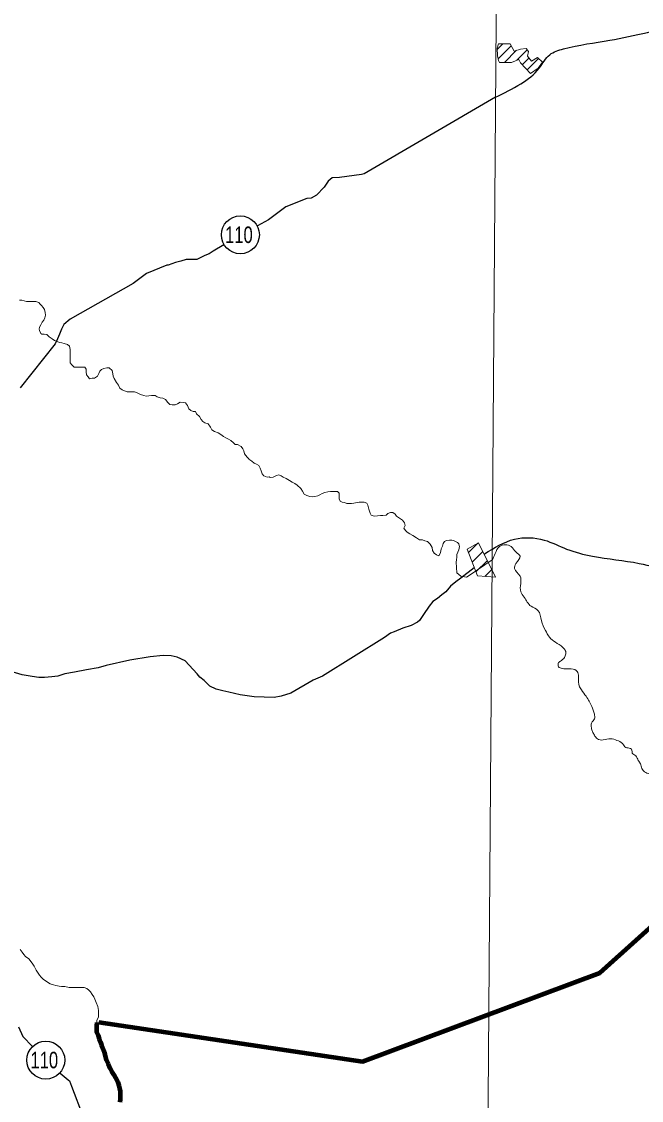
# Model space of a CAD drawing. Extents: x 553962 to 842807, y 8883888 to 9032388.
# Drawn here: x 616530 to 619151, y 8902192 to 8906757 of the extents above; entities that cross this region are included whole.
import ezdxf
from ezdxf.enums import TextEntityAlignment as Align

# ---------------------------------------------------------------- set-up
doc = ezdxf.new("R2010")
doc.units = 0
doc.header["$LTSCALE"] = 160
doc.layers.add('6', color=7, linetype='Continuous', lineweight=13)

msp = doc.modelspace()

# ---------------------------------------------------------------- linework, layer by layer
at = {"layer": '6'}
for p, q in [((618541.3, 8906638.8), (618565.2, 8906662.7)), ((618544.4, 8906599.4), (618599.8, 8906654.9)), ((618571.2, 8906583.9), (618623, 8906635.6)), ((618623.2, 8906593.4), (618667.4, 8906637.6)), ((618647.2, 8906575), (618675.6, 8906603.4)), ((618667.4, 8906552.7), (618715.2, 8906600.5)), ((618419.3, 8904510), (618459.5, 8904550.2)), ((618435.1, 8904469.2), (618480.5, 8904514.6)), ((618451, 8904428.5), (618499.1, 8904476.6)), ((618488.1, 8904409.1), (618517.7, 8904438.6))]:
    msp.add_line(p, q, dxfattribs=at)
for points in [[(618663, 8924716.1), (618558.3, 8909803.7), (618472.6, 8898203.5)], [(616520.7, 8905578.7), (616530.4, 8905578.1), (616540.1, 8905575.7), (616551, 8905573.2), (616566.8, 8905573.2), (616579.5, 8905573.2), (616589.8, 8905572), (616602.6, 8905568.4), (616607.5, 8905563.1), (616614.5, 8905555.9), (616620.6, 8905547.7), (616626.6, 8905538.5), (616629.6, 8905526.2), (616630.5, 8905514), (616627.4, 8905503.8), (616623.2, 8905493.7), (616616.5, 8905485.2), (616611.7, 8905474.3), (616606.2, 8905463.3), (616604.4, 8905455.4), (616605, 8905450), (616611.1, 8905437.2), (616614.7, 8905433.6), (616624.9, 8905433.6), (616637.1, 8905432.5), (616646.2, 8905423.2), (616659.3, 8905414), (616668.4, 8905406.8), (616679.6, 8905402.6), (616689.8, 8905398.5), (616699.9, 8905397.4), (616710.1, 8905395.3), (616724.3, 8905390.1), (616732.4, 8905382.9)], [(616732.4, 8905382.9), (616735.3, 8905369.7), (616735.3, 8905359.5), (616735.2, 8905344.2), (616735, 8905325.9), (616734.9, 8905312.6), (616742, 8905304.4), (616752.1, 8905295.2), (616762.3, 8905294.1), (616773.5, 8905294.1), (616784.7, 8905294), (616796.9, 8905294.9), (616802.9, 8905285.7), (616802.8, 8905275.5), (616804.8, 8905262.3), (616810.8, 8905254.1), (616816.9, 8905244.9), (616828.1, 8905247.9), (616838.2, 8905247.8), (616850.5, 8905255.9), (616856.7, 8905268.1), (616860.8, 8905277.2), (616867, 8905285.3), (616877.2, 8905288.3), (616890.4, 8905291.3), (616900.6, 8905291.2), (616912.7, 8905279.9), (616915.7, 8905266.7), (616916.6, 8905256.5), (616921.7, 8905246.2), (616931.7, 8905229.9), (616939.8, 8905218.6), (616945.8, 8905205.3), (616954.9, 8905199.2), (616965, 8905194), (616976.2, 8905190.9), (616986.4, 8905190.8)], [(616986.4, 8905190.8), (616996.5, 8905190.7), (617006.7, 8905189.7), (617018.9, 8905185.5), (617032.1, 8905179.3), (617046.3, 8905175.1), (617056.4, 8905172), (617067.6, 8905173), (617078.8, 8905174.9), (617094.1, 8905174.8), (617103.2, 8905169.7), (617116.4, 8905165.5), (617127.6, 8905163.4), (617137.7, 8905158.2), (617148.8, 8905144.9), (617156.9, 8905136.7), (617167.1, 8905135.7), (617179.3, 8905135.6), (617188.5, 8905139.6), (617200.7, 8905146.6), (617212.9, 8905144.5), (617223.1, 8905143.4), (617231.1, 8905132.2), (617237.1, 8905118.9), (617245.2, 8905110.7), (617255.4, 8905107.6), (617265.5, 8905106.5), (617269.5, 8905097.3), (617281.7, 8905086), (617289.7, 8905073.7), (617295.8, 8905064.5), (617304.9, 8905058.4), (617319.1, 8905054.2), (617329.2, 8905040.9), (617334.2, 8905029.7), (617345.3, 8905022.4), (617361.6, 8905016.2), (617371.7, 8905010.1), (617383.8, 8905001.8), (617392.9, 8904995.7), (617404.1, 8904990.5), (617415.2, 8904984.3), (617425.3, 8904975.1), (617432.4, 8904966.9), (617442.6, 8904966.8), (617458.8, 8904958.6), (617464.8, 8904949.3), (617469.9, 8904940.1), (617472.8, 8904927.9), (617483.6, 8904913.2), (617490, 8904906.8), (617490, 8904904.7), (617503.1, 8904897.1), (617513.3, 8904888.9), (617523.5, 8904884.2), (617532.9, 8904877.9), (617539.1, 8904867), (617542.2, 8904856.1), (617546.9, 8904843.6), (617554.7, 8904834.2), (617568.8, 8904829.5), (617576.6, 8904831.1), (617581.2, 8904827.9), (617594.2, 8904829.3), (617607.5, 8904836.4)], [(617607.5, 8904836.4), (617617.7, 8904839.4), (617627.8, 8904835.2), (617635.9, 8904829.1), (617649.1, 8904822.9), (617662.3, 8904815.6), (617674.4, 8904808.4), (617684.6, 8904802.2), (617695.7, 8904795.1), (617709.9, 8904780.7), (617716.9, 8904769.4), (617725, 8904757.2), (617736.1, 8904751), (617748.3, 8904746.8), (617758.4, 8904745.8), (617769.6, 8904746.7), (617781.9, 8904749.7), (617791.1, 8904753.7), (617800.2, 8904759.7), (617812.5, 8904763.7), (617824.7, 8904767.7), (617835.9, 8904768.7), (617855.2, 8904768.6), (617865.4, 8904768.5), (617872.5, 8904761.3), (617872.4, 8904748.1), (617872.3, 8904737.9), (617876.3, 8904727.7), (617885.5, 8904723.5), (617895.6, 8904722.4), (617904.7, 8904718.3), (617914.9, 8904718.2), (617925.1, 8904718.2), (617935.3, 8904719.1), (617957.7, 8904723.1), (617967.8, 8904723), (617979, 8904724)], [(617979, 8904724), (617989.2, 8904719.8), (617993.2, 8904710.6), (617998.2, 8904693.3), (618004.1, 8904676.9), (618008.2, 8904667.7), (618020.3, 8904663.6), (618034.6, 8904665.5), (618046.8, 8904667.5), (618057, 8904667.4), (618071.2, 8904668.3), (618078.4, 8904675.4), (618089.6, 8904679.4), (618099.8, 8904679.4), (618108.9, 8904672.2), (618114.9, 8904664), (618124.1, 8904658.8), (618132.2, 8904652.7), (618140.2, 8904646.5), (618148.3, 8904635.3), (618151.3, 8904625.1), (618146.1, 8904612.9), (618153.2, 8904603.6), (618160.2, 8904596.5), (618171.4, 8904589.3), (618184.6, 8904582.1), (618199.8, 8904572.8), (618212.9, 8904564.6), (618225.1, 8904563.4), (618235.3, 8904560.3), (618245.4, 8904556.2), (618257.6, 8904545.9), (618265.6, 8904531.6), (618267.5, 8904519.4), (618274.6, 8904508.1), (618283.7, 8904500.9), (618293.8, 8904496.8), (618300, 8904505.9), (618303.1, 8904516.1), (618304.2, 8904526.3), (618309, 8904537.8), (618312.5, 8904548.5), (618317.6, 8904556.7), (618326.8, 8904561.1), (618339.4, 8904562.8), (618348.3, 8904562.8), (618355.5, 8904561.1), (618364.4, 8904557.5), (618373.3, 8904552.1), (618378.7, 8904546.7), (618380.5, 8904539.6), (618381.6, 8904536), (618378.4, 8904521.7), (618374.3, 8904511.6), (618370.2, 8904501.4), (618370.1, 8904491.2), (618369, 8904479), (618367.9, 8904468.8), (618370.7, 8904425), (618386.8, 8904409.6), (618410.9, 8904405.3), (618427, 8904416), (618519.7, 8904479.2)], [(616524, 8902830.2), (616532, 8902818.9), (616539.1, 8902809.7), (616546.1, 8902800.5), (616560.3, 8902791.2), (616570.4, 8902777.9), (616577.4, 8902768.7), (616582.5, 8902759.5), (616591.5, 8902743.1), (616599.6, 8902730.8), (616605.6, 8902721.6), (616612.7, 8902713.4), (616622.8, 8902703.2), (616633.9, 8902696), (616643, 8902689.8), (616651.3, 8902684.9), (616664.3, 8902680.5), (616674.5, 8902677.4), (616688.7, 8902675.3), (616698.9, 8902674.2), (616712.1, 8902674.1), (616730.4, 8902669.9), (616742.6, 8902669.8), (616754.8, 8902669.7), (616772.1, 8902669.6), (616784.3, 8902669.6), (616794.5, 8902669.5), (616805.6, 8902665.3), (616813.7, 8902658.2), (616820.8, 8902651), (616828.8, 8902639.7), (616834.9, 8902629.5), (616838.9, 8902620.3), (616844.9, 8902606), (616851.9, 8902588.6), (616854.8, 8902572.3), (616854.7, 8902555), (616854.6, 8902543.8), (616847.4, 8902531.6), (616847.3, 8902519.4), (616847.2, 8902508.2), (616846.1, 8902492.9), (616846.1, 8902481.7), (616853.1, 8902466.4), (616858.1, 8902452.1), (616863, 8902437.8), (616868, 8902425.5), (616872, 8902415.3), (616879.1, 8902399), (616882, 8902385.7), (616885, 8902374.5), (616888, 8902363.3), (616896, 8902345.9)], [(616896, 8902345.9), (616900, 8902336.7), (616905, 8902326.5), (616912, 8902312.2), (616920.1, 8902299.9), (616927.1, 8902286.6), (616936.1, 8902269.2), (616941.1, 8902254.9), (616944.1, 8902243.7), (616947.1, 8902230.4), (616947, 8902218.2), (616946.9, 8902207), (616946.8, 8902196.8), (616945.7, 8902184.6)]]:
    msp.add_lwpolyline(points, dxfattribs=at)
for points in [[(618595.3, 8906663), (618545.6, 8906662.6), (618541.1, 8906644.9), (618542, 8906612), (618545.6, 8906593), (618551, 8906583.5), (618601.6, 8906584.4), (618631.9, 8906597.1), (618640, 8906583.1), (618681.6, 8906537), (618714.5, 8906560), (618732.6, 8906584.9), (618710.5, 8906604.7), (618686.5, 8906589.8), (618669.4, 8906611.1), (618673, 8906630.5), (618662.6, 8906643.6), (618639.6, 8906640.9), (618612.5, 8906632.3)], [(618462.3, 8904551.7), (618413.4, 8904525.1), (618457.8, 8904411), (618533.6, 8904406.1)]]:
    msp.add_lwpolyline(points, close=True, dxfattribs=at)
at = {"layer": '6', "lineweight": 25}
for points in [[(618533.2, 8906436.6), (617978.2, 8906112.6), (617967, 8906109.6), (617874.3, 8906097.6), (617843.7, 8906095.6), (617826.3, 8906081.3), (617808.9, 8906055.9), (617776.2, 8906022.3), (617753.7, 8906010.2), (617735.4, 8906008.2), (617647.6, 8905973.7), (617574.1, 8905917.8), (617526.6, 8905893.4)], [(617384.3, 8905811.9), (617340.2, 8905785.8), (617322.9, 8905774.6), (617304.5, 8905767.5), (617270.8, 8905750.2), (617226, 8905750.3), (617202.5, 8905743.2), (617180.1, 8905738.2), (617149.5, 8905726), (617144.4, 8905726), (617057.7, 8905690.5), (617001.5, 8905648.8), (616735, 8905497.5), (616708.4, 8905475.2), (616698.2, 8905454.8), (616689.9, 8905434.4), (616681.7, 8905415.1), (616671.4, 8905393.7), (616524, 8905206.5)], [(618442.8, 8904444.9), (618387.6, 8904401.3), (618365.2, 8904386.1), (618343.7, 8904367.8), (618323.2, 8904343.3), (618306.9, 8904331.1), (618288.5, 8904315.9), (618269.1, 8904302.7), (618252.7, 8904283.3), (618229.2, 8904247.7), (618212.8, 8904222.3), (618203.6, 8904215.2), (618177, 8904202), (618142.3, 8904189.8), (618104.6, 8904174.6), (618089.3, 8904169.5), (618064.8, 8904150.2), (617802.3, 8903987.7), (617762.5, 8903970.5), (617667.6, 8903914.6), (617626.8, 8903902.4), (617597.2, 8903896.4), (617513.6, 8903899.6), (617454.6, 8903907.9), (617406.7, 8903919.2), (617380.3, 8903925.3), (617352.8, 8903931.5), (617326.3, 8903944.8), (617302, 8903969.3), (617283.7, 8903982.5), (617271.5, 8903996.8), (617239, 8904033.6), (617221.8, 8904051.9), (617187.2, 8904067.3), (617162.8, 8904073.4), (617128.1, 8904074.5), (617074.1, 8904069.5), (616987.5, 8904055.4), (616887.5, 8904032.2), (616853.9, 8904022.1), (616803.9, 8904014), (616752.9, 8904003.9), (616713.2, 8903996.8), (616683.6, 8903987.7), (616658.1, 8903983.7), (616626.5, 8903981.7), (616602.1, 8903981.8), (616574.6, 8903984.9), (616532.8, 8903993.1), (616245.8, 8904077.2)], [(616516.1, 8902503.6), (616535.3, 8902462.8), (616575.3, 8902420.1)], [(616692.6, 8902307.3), (616726.2, 8902278.1), (616732.3, 8902274), (616740.4, 8902251.6), (616789.8, 8902122.1), (616817, 8902022.2), (616832.2, 8902001.8)]]:
    msp.add_lwpolyline(points, dxfattribs=at)
at = {"layer": '6', "lineweight": 90}
for points in [[(616856.8, 8902522.4), (617971.6, 8902356.9), (618975.2, 8902732.2), (619784.7, 8903460.5), (620099.8, 8903345.9), (620793.1, 8903911.7), (622044.3, 8904602.1)], [(616847.3, 8902521.6), (616847.3, 8902519.4), (616847.2, 8902508.2), (616846.1, 8902492.9), (616846.1, 8902481.7), (616853.1, 8902466.4), (616858.1, 8902452.1), (616863, 8902437.8), (616868, 8902425.5), (616872, 8902415.3), (616879.1, 8902399), (616882, 8902385.7), (616885, 8902374.5), (616888, 8902363.3), (616896, 8902345.9)], [(616896, 8902345.9), (616900, 8902336.7), (616905, 8902326.5), (616912, 8902312.2), (616920.1, 8902299.9), (616927.1, 8902286.6), (616936.1, 8902269.2), (616941.1, 8902254.9), (616944.1, 8902243.7), (616947.1, 8902230.4), (616947, 8902218.2), (616946.9, 8902207), (616946.8, 8902196.8), (616945.7, 8902184.6)]]:
    msp.add_lwpolyline(points, dxfattribs=at)
at = {"layer": '6', "lineweight": 25}
for centre in [(617454.9, 8905854.7), (616632.2, 8902362.2)]:
    msp.add_circle(centre, 80.3, dxfattribs=at)
for points in [[(618533.2, 8906436.6), (618640.7, 8906494.3), (618718.4, 8906559.7), (618763.3, 8906617), (618820.6, 8906641.5), (619016.9, 8906678.3), (619176.3, 8906711), (619254, 8906735.6), (619352.2, 8906825.5), (619442.1, 8906899.1), (619532.1, 8907042.2), (619630.2, 8907238.5), (619687.5, 8907398), (619720.2, 8907528.8), (619740.6, 8907635.2), (619765.2, 8907684.2), (619806, 8907741.5), (619834.7, 8907831.4), (619871.5, 8907884.6), (619957.3, 8907905), (620026.8, 8907892.8), (620094.6, 8907904)], [(618487.4, 8904504.8), (618614.5, 8904566.7), (618739.5, 8904562.9), (618834.2, 8904525), (618944, 8904494.7), (619141, 8904464.4), (619269.8, 8904426.5), (619413.7, 8904347), (619610.7, 8904248.5), (619898.6, 8904070.5), (620175.1, 8903918.9), (620288.7, 8903884.9), (620489.5, 8903873.5), (620815.2, 8903858.3), (621019.8, 8903831.8), (621319, 8903718.2), (621610.7, 8903631.1), (621785, 8903608.3), (621841.8, 8903604.6), (621917.5, 8903551.5), (622012.2, 8903479.6), (622084.2, 8903426.5), (622194.1, 8903396.2), (622315.3, 8903388.6)]]:
    msp.add_spline(points, degree=3, dxfattribs=at)
at = {"layer": '6'}
msp.add_spline([(618519.7, 8904479.2), (618532.8, 8904506.8), (618550.3, 8904535.8), (618599.7, 8904535.8), (618620.1, 8904512.6), (618637.5, 8904495.1), (618620.1, 8904463.1), (618614.2, 8904442.8), (618637.5, 8904410.8), (618640.4, 8904378.8), (618640.4, 8904343.9), (618655, 8904320.7), (618684, 8904282.9), (618713.1, 8904265.4), (618727.6, 8904221.8), (618744.8, 8904180.8), (618762.3, 8904151.5), (618786.7, 8904131), (618818.9, 8904108.6), (618830.6, 8904091), (618828.7, 8904072.5), (618812.1, 8904053), (618800.4, 8904044.2), (618800.4, 8904026.6), (618815, 8904019.8), (618846.2, 8904017.8), (618874.5, 8904011), (618881.3, 8904002.2), (618885.2, 8903978.8), (618887.2, 8903945.6), (618897, 8903929), (618916.5, 8903901.7), (618940.9, 8903858.8), (618951.6, 8903826.6), (618952.6, 8903806.1), (618939.9, 8903788.6), (618938.9, 8903768.1), (618943.8, 8903752.4), (618951.6, 8903737.8), (618964.3, 8903721.2), (618988.7, 8903717.3), (619019.9, 8903722.2), (619047.2, 8903715.4), (619070.6, 8903701.7), (619085.3, 8903685.1), (619103.8, 8903681.2), (619110.6, 8903673.4), (619111.6, 8903661.7), (619127.2, 8903649.3), (619137, 8903630.8), (619146.7, 8903616.1), (619152.6, 8903596.6), (619164.3, 8903581.9), (619184.8, 8903573.2), (619214.1, 8903563.4)], degree=3, dxfattribs=at)

# ---------------------------------------------------------------- texts
at = {"layer": '6', "width": 0.75}
for p in [(617448.6, 8905820), (616625.8, 8902327.6)]:
    msp.add_text('110', height=70, dxfattribs=at).set_placement(p, align=Align.CENTER)

doc.saveas('drawing.dxf')
